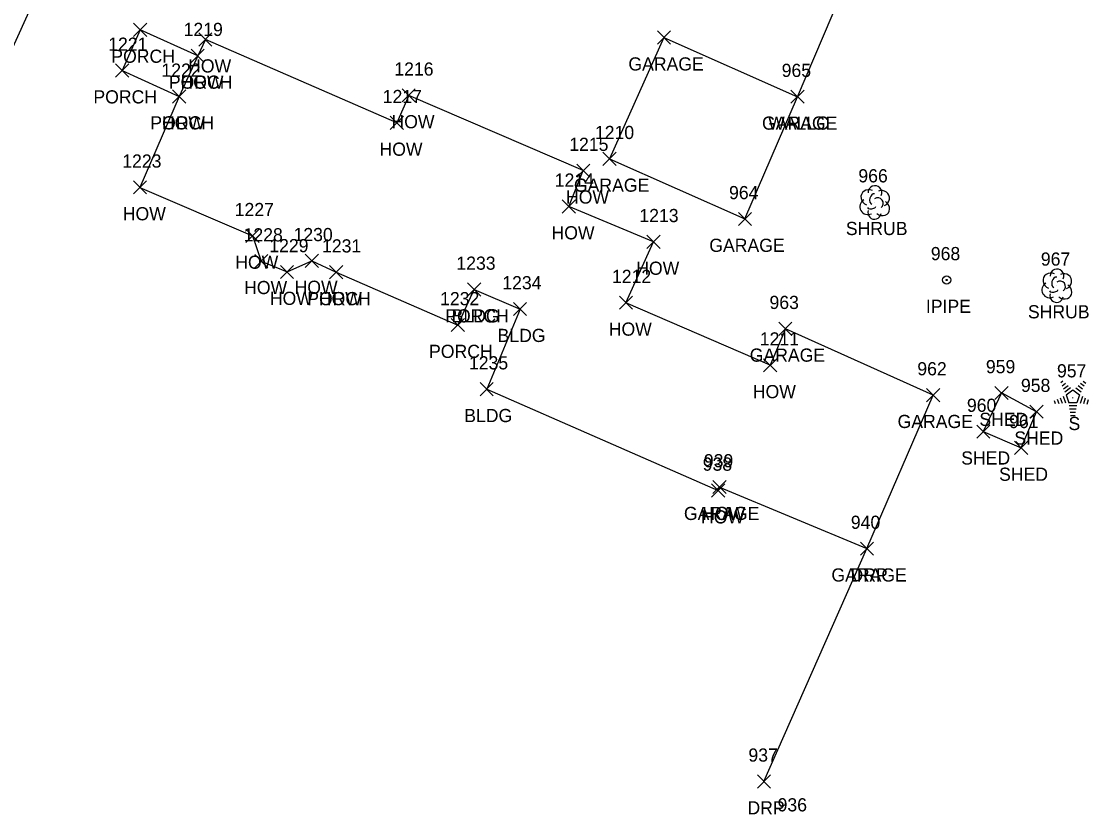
# Model space of a CAD drawing. Extents: x 1767353 to 1772625, y 740790 to 747702.
# Drawn here: x 1770037.2 to 1770199.2, y 742293.3 to 742414.3 of the extents above; entities that cross this region are included whole.
import ezdxf

# ---------------------------------------------------------------- set-up
doc = ezdxf.new("R2010")
doc.units = 0
for name, color, linetype in [('L_A', 7, 'Continuous'), ('L_I', 7, 'Continuous'), ('L_TIC', 7, 'Continuous'), ('LBC', 7, 'Continuous'), ('LBF', 7, 'Continuous'), ('LSH', 7, 'Continuous'), ('LTC', 7, 'Continuous'), ('LW', 7, 'Continuous'), ('M_A', 7, 'Continuous'), ('M_I', 7, 'Continuous'), ('MPIP', 7, 'Continuous'), ('R_A', 7, 'Continuous'), ('R_I', 7, 'Continuous'), ('R_TIC', 7, 'Continuous'), ('RDP', 7, 'Continuous'), ('RSW', 7, 'Continuous')]:
    doc.layers.add(name, color=color, linetype=linetype)

msp = doc.modelspace()

# ---------------------------------------------------------------- linework, layer by layer
at = {"layer": 'L_TIC'}
for points in [[(1770054.25, 742412.04), (1770056.25, 742414.04)], [(1770056.25, 742412.04), (1770054.25, 742414.04)], [(1770133.76, 742410.87), (1770135.76, 742412.87)], [(1770135.76, 742410.87), (1770133.76, 742412.87)], [(1770064.15, 742410.57), (1770066.15, 742412.57)], [(1770066.15, 742410.57), (1770064.15, 742412.57)], [(1770062.98, 742408.11), (1770064.98, 742410.11)], [(1770064.98, 742408.11), (1770062.98, 742410.11)], [(1770062.98, 742408.11), (1770064.98, 742410.11)], [(1770064.98, 742408.11), (1770062.98, 742410.11)], [(1770051.53, 742405.87), (1770053.53, 742407.87)], [(1770053.53, 742405.87), (1770051.53, 742407.87)], [(1770060.17, 742401.93), (1770062.17, 742403.93)], [(1770062.17, 742401.93), (1770060.17, 742403.93)], [(1770060.17, 742401.93), (1770062.17, 742403.93)], [(1770062.17, 742401.93), (1770060.17, 742403.93)], [(1770095.01, 742402.1), (1770097.01, 742404.1)], [(1770097.01, 742402.1), (1770095.01, 742404.1)], [(1770154.04, 742401.89), (1770156.04, 742403.89)], [(1770156.04, 742401.89), (1770154.04, 742403.89)], [(1770154.04, 742401.89), (1770156.04, 742403.89)], [(1770156.04, 742401.89), (1770154.04, 742403.89)], [(1770093.2, 742397.93), (1770095.2, 742399.93)], [(1770095.2, 742397.93), (1770093.2, 742399.93)], [(1770125.49, 742392.47), (1770127.49, 742394.47)], [(1770127.49, 742392.47), (1770125.49, 742394.47)], [(1770121.51, 742390.67), (1770123.51, 742392.67)], [(1770123.51, 742390.67), (1770121.51, 742392.67)], [(1770054.22, 742388.13), (1770056.22, 742390.13)], [(1770056.22, 742388.13), (1770054.22, 742390.13)], [(1770119.31, 742385.24), (1770121.31, 742387.24)], [(1770121.31, 742385.24), (1770119.31, 742387.24)], [(1770146.05, 742383.34), (1770148.05, 742385.34)], [(1770148.05, 742383.34), (1770146.05, 742385.34)], [(1770071.29, 742380.77), (1770073.29, 742382.77)], [(1770073.29, 742380.77), (1770071.29, 742382.77)], [(1770132.16, 742379.86), (1770134.16, 742381.86)], [(1770134.16, 742379.86), (1770132.16, 742381.86)], [(1770072.64, 742376.93), (1770074.64, 742378.93)], [(1770074.64, 742376.93), (1770072.64, 742378.93)], [(1770080.3, 742376.97), (1770082.3, 742378.97)], [(1770082.3, 742376.97), (1770080.3, 742378.97)], [(1770076.55, 742375.29), (1770078.55, 742377.29)], [(1770078.55, 742375.29), (1770076.55, 742377.29)], [(1770083.99, 742375.25), (1770085.99, 742377.25)], [(1770085.99, 742375.25), (1770083.99, 742377.25)], [(1770083.99, 742375.25), (1770085.99, 742377.25)], [(1770085.99, 742375.25), (1770083.99, 742377.25)], [(1770104.94, 742372.63), (1770106.94, 742374.63)], [(1770106.94, 742372.63), (1770104.94, 742374.63)], [(1770104.94, 742372.63), (1770106.94, 742374.63)], [(1770106.94, 742372.63), (1770104.94, 742374.63)], [(1770127.99, 742370.62), (1770129.99, 742372.62)], [(1770129.99, 742370.62), (1770127.99, 742372.62)], [(1770111.91, 742369.66), (1770113.91, 742371.66)], [(1770113.91, 742369.66), (1770111.91, 742371.66)], [(1770102.47, 742367.24), (1770104.47, 742369.24)], [(1770104.47, 742367.24), (1770102.47, 742369.24)], [(1770152.19, 742366.67), (1770154.19, 742368.67)], [(1770154.19, 742366.67), (1770152.19, 742368.67)], [(1770149.87, 742361.13), (1770151.87, 742363.13)], [(1770151.87, 742361.13), (1770149.87, 742363.13)], [(1770106.85, 742357.5), (1770108.85, 742359.5)], [(1770108.85, 742357.5), (1770106.85, 742359.5)], [(1770174.63, 742356.6), (1770176.63, 742358.6)], [(1770176.63, 742356.6), (1770174.63, 742358.6)], [(1770185, 742356.92), (1770187, 742358.92)], [(1770187, 742356.92), (1770185, 742358.92)], [(1770190.31, 742354.08), (1770192.31, 742356.08)], [(1770192.31, 742354.08), (1770190.31, 742356.08)], [(1770182.24, 742351.06), (1770184.24, 742353.06)], [(1770184.24, 742351.06), (1770182.24, 742353.06)], [(1770187.99, 742348.59), (1770189.99, 742350.59)], [(1770189.99, 742348.59), (1770187.99, 742350.59)], [(1770142.19, 742342.64), (1770144.19, 742344.64)], [(1770144.19, 742342.64), (1770142.19, 742344.64)], [(1770142.19, 742342.64), (1770144.19, 742344.64)], [(1770144.19, 742342.64), (1770142.19, 742344.64)], [(1770142, 742342.12), (1770144, 742344.12)], [(1770144, 742342.12), (1770142, 742344.12)], [(1770164.58, 742333.3), (1770166.58, 742335.3)], [(1770166.58, 742333.3), (1770164.58, 742335.3)]]:
    msp.add_lwpolyline(points, dxfattribs=at)
at = {"layer": 'LBC'}
for points in [[(1770150.87, 742362.13), (1770128.99, 742371.62), (1770133.16, 742380.86), (1770120.31, 742386.24), (1770122.51, 742391.67), (1770096.01, 742403.1), (1770094.2, 742398.93), (1770065.15, 742411.57), (1770063.98, 742409.11), (1770061.17, 742402.93), (1770055.22, 742389.13), (1770072.29, 742381.77), (1770073.64, 742377.93), (1770077.55, 742376.29), (1770081.3, 742377.97), (1770084.99, 742376.25)], [(1770134.76, 742411.87), (1770126.49, 742393.47)], [(1770134.76, 742411.87), (1770155.04, 742402.89)], [(1770147.05, 742384.34), (1770155.04, 742402.89)], [(1770126.49, 742393.47), (1770147.05, 742384.34)], [(1770105.94, 742373.63), (1770112.91, 742370.66), (1770107.85, 742358.5)], [(1770143.19, 742343.64), (1770165.58, 742334.3), (1770175.63, 742357.6), (1770153.19, 742367.67)], [(1770153.19, 742367.67), (1770150.87, 742362.13)], [(1770107.85, 742358.5), (1770143, 742343.12)], [(1770191.31, 742355.08), (1770186, 742357.92), (1770183.24, 742352.06), (1770188.99, 742349.59)], [(1770188.99, 742349.59), (1770191.31, 742355.08)], [(1770143, 742343.12), (1770143.19, 742343.64)]]:
    msp.add_lwpolyline(points, dxfattribs=at)
at = {"layer": 'LBF'}
for points in [[(1770063.98, 742409.11), (1770055.25, 742413.04), (1770052.53, 742406.87), (1770061.17, 742402.93)], [(1770084.99, 742376.25), (1770103.47, 742368.24), (1770105.94, 742373.63)]]:
    msp.add_lwpolyline(points, dxfattribs=at)
at = {"layer": 'LSH'}
for p, q in [((1770166.74, 742386.89), (1770166.74, 742386.89)), ((1770166.74, 742386.89), (1770166.74, 742386.89)), ((1770194.38, 742374.25), (1770194.38, 742374.25)), ((1770194.38, 742374.25), (1770194.38, 742374.25))]:
    msp.add_line(p, q, dxfattribs=at)
for centre in [(1770166.79, 742388.32), (1770194.42, 742375.69)]:
    msp.add_arc(centre, 1.05, 335.5272, 180.9563, dxfattribs=at)
for centre, major_axis, ratio, start_param, end_param in [((1770165.95, 742387.56), (1.21, -0.51), 0.895232, 1.570796, 4.712389), ((1770167.78, 742387.47), (-1.14, -0.48), 0.949671, 1.570796, 4.712389), ((1770165.66, 742386.18), (0.58, -1.04), 0.959034, 3.141593, 6.283185), ((1770166.53, 742387.35), (-0.208, -0.792), 0.645439, 3.141593, 6.283185), ((1770167.24, 742386.72), (-0.5, 0.667), 0.989748, 3.141593, 6.283185), ((1770167.74, 742386.06), (-1.09, 0.79), 0.841452, 1.570796, 4.712389), ((1770166.74, 742385.39), (0.26, 1.06), 0.942809, 1.570796, 4.712389), ((1770166.28, 742386.14), (-0.625, -0.083), 0.423636, 0, 3.141593), ((1770193.59, 742374.92), (1.21, -0.51), 0.895232, 1.570796, 4.712389), ((1770194.17, 742374.71), (-0.208, -0.792), 0.645439, 3.141593, 6.283185), ((1770195.42, 742374.84), (-1.14, -0.48), 0.949671, 1.570796, 4.712389), ((1770193.29, 742373.55), (0.58, -1.04), 0.959034, 3.141593, 6.283185), ((1770194.88, 742374.09), (-0.5, 0.667), 0.989748, 3.141593, 6.283185), ((1770195.38, 742373.42), (-1.09, 0.79), 0.841452, 1.570796, 4.712389), ((1770194.38, 742372.75), (0.26, 1.06), 0.942809, 1.570796, 4.712389), ((1770193.92, 742373.5), (-0.625, -0.083), 0.423636, 0, 3.141593)]:
    msp.add_ellipse(centre, major_axis=major_axis, ratio=ratio, start_param=start_param, end_param=end_param, dxfattribs=at)
at = {"layer": 'LTC'}
for p, q in [((1770194.98, 742359.5), (1770195.33, 742359.76)), ((1770195.19, 742359.03), (1770195.71, 742359.42)), ((1770198, 742359.39), (1770198.55, 742358.99)), ((1770198.37, 742359.74), (1770198.79, 742359.43)), ((1770195.4, 742358.57), (1770196.1, 742359.08)), ((1770195.6, 742358.1), (1770196.48, 742358.74)), ((1770195.83, 742357.65), (1770196.84, 742358.38)), ((1770195.83, 742357.65), (1770196.22, 742356.45)), ((1770196.84, 742358.38), (1770197.84, 742357.66)), ((1770197.26, 742358.69), (1770198.07, 742358.11)), ((1770197.84, 742357.66), (1770197.45, 742356.45)), ((1770197.63, 742359.04), (1770198.31, 742358.55)), ((1770194.01, 742356.78), (1770194.16, 742356.31)), ((1770194.46, 742356.99), (1770194.68, 742356.34)), ((1770194.92, 742357.21), (1770195.19, 742356.38)), ((1770195.37, 742357.43), (1770195.71, 742356.41)), ((1770197.45, 742356.45), (1770196.22, 742356.45)), ((1770198.28, 742357.39), (1770197.94, 742356.35)), ((1770198.72, 742357.14), (1770198.43, 742356.25)), ((1770199.16, 742356.89), (1770198.93, 742356.16)), ((1770197.41, 742355.95), (1770196.26, 742355.95)), ((1770197.32, 742355.45), (1770196.34, 742355.45)), ((1770197.24, 742354.95), (1770196.41, 742354.95)), ((1770197.16, 742354.45), (1770196.48, 742354.45))]:
    msp.add_line(p, q, dxfattribs=at)
at = {"layer": 'LW'}
msp.add_lwpolyline([(1770155.04, 742402.89), (1770169.51, 742436.9), (1770159.15, 742441.25)], dxfattribs=at)
at = {"layer": 'MPIP'}
for radius in [0.625, 0.0833]:
    msp.add_circle((1770177.68, 742375.08), radius, dxfattribs=at)
at = {"layer": 'R_TIC'}
for points in [[(1770164.58, 742333.3), (1770166.58, 742335.3)], [(1770166.58, 742333.3), (1770164.58, 742335.3)], [(1770148.94, 742297.96), (1770150.94, 742299.96)], [(1770150.94, 742297.96), (1770148.94, 742299.96)]]:
    msp.add_lwpolyline(points, dxfattribs=at)
at = {"layer": 'RDP'}
msp.add_lwpolyline([(1770149.94, 742298.96), (1770165.58, 742334.3)], dxfattribs=at)
at = {"layer": 'RSW'}
msp.add_lwpolyline([(1770098.34, 742558.06), (1770101.99, 742556.46), (1770027.61, 742392.19), (1769957.88, 742235.71), (1769937.16, 742186.55), (1769936.48, 742178.62)], dxfattribs=at)

# ---------------------------------------------------------------- texts
at = {"layer": 'L_A'}
for s, p in [('PORCH', (1770050.87, 742408.04)), ('HOW', (1770062.53, 742406.57)), ('GARAGE', (1770129.36, 742406.87)), ('PORCH', (1770059.6, 742404.11)), ('HOW', (1770061.37, 742404.11)), ('PORCH', (1770048.15, 742401.87)), ('PORCH', (1770056.79, 742397.93)), ('HOW', (1770058.55, 742397.93)), ('HOW', (1770093.4, 742398.1)), ('GARAGE', (1770149.64, 742397.89)), ('WALLC', (1770150.58, 742397.89)), ('HOW', (1770091.58, 742393.93)), ('GARAGE', (1770121.09, 742388.47)), ('HOW', (1770119.89, 742386.67)), ('HOW', (1770052.61, 742384.13)), ('SHRUB', (1770162.37, 742381.89)), ('HOW', (1770117.69, 742381.24)), ('GARAGE', (1770141.64, 742379.34)), ('HOW', (1770069.68, 742376.77)), ('HOW', (1770130.55, 742375.86)), ('HOW', (1770071.03, 742372.93)), ('HOW', (1770078.69, 742372.97)), ('HOW', (1770074.94, 742371.29)), ('PORCH', (1770080.61, 742371.25)), ('HOW', (1770082.37, 742371.25)), ('PORCH', (1770101.56, 742368.63)), ('BLDG', (1770102.53, 742368.63)), ('SHRUB', (1770190.01, 742369.25)), ('BLDG', (1770109.5, 742365.66)), ('HOW', (1770126.38, 742366.62)), ('PORCH', (1770099.1, 742363.24)), ('GARAGE', (1770147.78, 742362.67)), ('HOW', (1770148.25, 742357.13)), ('BLDG', (1770104.44, 742353.5)), ('GARAGE', (1770170.22, 742352.6)), ('SHED', (1770182.64, 742352.92)), ('S', (1770196.17, 742352.29)), ('SHED', (1770187.95, 742350.08)), ('SHED', (1770179.88, 742347.06)), ('SHED', (1770185.63, 742344.59)), ('GARAGE', (1770137.79, 742338.64)), ('HOW', (1770140.39, 742338.12)), ('HOW', (1770140.58, 742338.64)), ('GARAGE', (1770160.18, 742329.3))]:
    msp.add_text(s, height=2, dxfattribs=at).set_placement(p)
at = {"layer": 'L_I'}
for s, p in [('1219', (1770061.85, 742412.11)), ('1219', (1770061.85, 742412.11)), ('1221', (1770050.4, 742409.87)), ('1222', (1770058.48, 742405.93)), ('1222', (1770058.48, 742405.93)), ('1216', (1770093.83, 742406.1)), ('965', (1770152.63, 742405.89)), ('965', (1770152.63, 742405.89)), ('1217', (1770092.07, 742401.93)), ('1210', (1770124.28, 742396.47)), ('1215', (1770120.38, 742394.67)), ('1223', (1770052.53, 742392.13)), ('966', (1770164.27, 742389.89)), ('1214', (1770118.18, 742389.24)), ('964', (1770144.64, 742387.34)), ('1227', (1770069.6, 742384.77)), ('1213', (1770131.03, 742383.86)), ('1228', (1770070.95, 742380.93)), ('1230', (1770078.53, 742380.97)), ('1229', (1770074.85, 742379.29)), ('1231', (1770082.86, 742379.25)), ('1231', (1770082.86, 742379.25)), ('1233', (1770103.25, 742376.63)), ('1233', (1770103.25, 742376.63)), ('967', (1770191.97, 742377.25)), ('1234', (1770110.22, 742373.66)), ('1212', (1770126.87, 742374.62)), ('1232', (1770100.78, 742371.24)), ('963', (1770150.78, 742370.67)), ('1211', (1770149.31, 742365.13)), ('1235', (1770105.16, 742361.5)), ('962', (1770173.22, 742360.6)), ('959', (1770183.63, 742360.92)), ('957', (1770194.42, 742360.29)), ('958', (1770188.95, 742358.08)), ('960', (1770180.75, 742355.06)), ('961', (1770187.15, 742352.59)), ('938', (1770140.64, 742346.12)), ('939', (1770140.82, 742346.64)), ('939', (1770140.82, 742346.64)), ('940', (1770163.13, 742337.3)), ('936', (1770152.01, 742294.41))]:
    msp.add_text(s, height=2, dxfattribs=at).set_placement(p)
at = {"layer": 'LTC'}
msp.add_text('.', height=1.04, rotation=270, dxfattribs=at).set_placement((1770196.72, 742357.39))
at = {"layer": 'M_A'}
msp.add_text('IPIPE', height=2, dxfattribs=at).set_placement((1770174.52, 742370.08))
at = {"layer": 'M_I'}
msp.add_text('968', height=2, dxfattribs=at).set_placement((1770175.27, 742378.08))
at = {"layer": 'R_A'}
for p in [(1770163.07, 742329.3), (1770147.43, 742293.96)]:
    msp.add_text('DRP', height=2, dxfattribs=at).set_placement(p)
at = {"layer": 'R_I'}
for s, p in [('940', (1770163.13, 742337.3)), ('937', (1770147.58, 742301.96))]:
    msp.add_text(s, height=2, dxfattribs=at).set_placement(p)

doc.saveas('drawing.dxf')
